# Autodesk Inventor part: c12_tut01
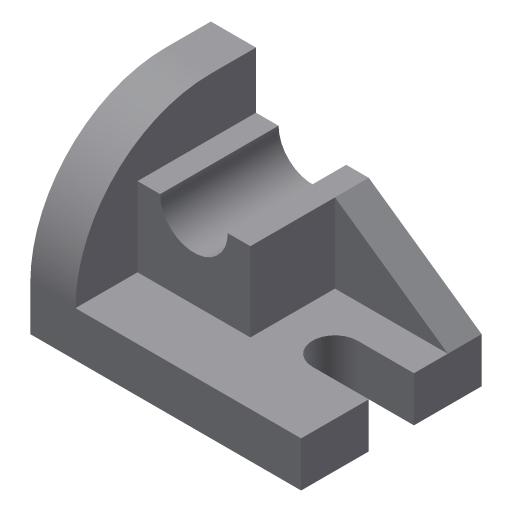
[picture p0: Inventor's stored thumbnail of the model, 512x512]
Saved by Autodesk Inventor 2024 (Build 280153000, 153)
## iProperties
Shininess: 77.0
Length Units: 11269
Angle Units: 11279
Time Units: 11290
Mass Units: 11283
Length Display Precision: 3
Angle Display Precision: 2
Created: 2001-11
Part Number: c12_tut01
Document SubType Name: Modeling
Designer: Renu Muthoo
Density: 1 g/cm^3
Material: Generic
Appearance: Default
Density: 0.0
Volumn: 0.0
Area: 0.0
PropertySet Name: Model Information
Control State: 0
Master: False
Checked Out: False
Author: Renu Muthoo
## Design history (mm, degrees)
sketch "Sketch1"
  geometry: L1 (-48, 36)-(48, 36); L2 (48, -28)-(-48, -28); L3 (-48, -28)-(-48, 36); L4 (48, 12)-(28, 12); L5 (28, -4)-(48, -4); L6 (48, 36)-(48, 12); L7 (48, -4)-(48, -28); A1 r 8 centre (28, 4) between (28, 12) and (28, -4)
  constraints: 14 end point, 4 parallel, 3 perpendicular, 2 point on circle, 2 tangent, 1 centre point, 1 collinear, 1 horizontal
  dimensions: "d0" = 96 distance of L2.start L2.end; "d1" = 64 distance of L2.end L1.start; "d2" = 20 distance of L4.start L4.end; "d3" = 24 distance between parallel lines of L2 L5; "d4" = 16 distance between parallel lines of L4 L5
extrude "Extrusion1" new body sketch "Sketch1" distance "d5" = 16; taper "d6" = 0 deg
sketch "Sketch2"
  geometry: L1 (16, 64)-(64, 64); L2 (64, 64)-(64, 48); L3 (16, 0)-(16, 0); L4 (16, 0)-(16, 64); L5 (0, 64)-(16, 64) reference; L6 (16, 0)-(16, 64) reference; L7 (0, 0)-(16, 0) reference; L8 (0, 0)-(0, 64) reference; A1 r 48 centre (16, 48) between (16, 0) and (64, 48)
  constraints: 8 end point, 3 collinear, 3 perpendicular, 2 point on circle, 2 tangent, 1 centre point, 1 horizontal
  dimensions: "d7" = 64 distance between parallel lines of L2 L8; "d8" = 48 radius of A1
extrude "Extrusion2" join sketch "Sketch2" distance "d9" = 16; taper "d10" = 0 deg
sketch "Sketch3"
  geometry: L1 (16, -44)-(16, -16); L2 (16, -16)-(56, -16); L3 (56, -16)-(56, -44); L4 (56, -44)-(48, -44); L5 (24, -44)-(16, -44); L6 (16, -64)-(16, -16) reference; L7 (16, -16)-(96, -16) reference; A1 r 12 centre (36, -44) between (48, -44) and (24, -44)
  constraints: 10 end point, 3 collinear, 3 parallel, 2 equal length, 2 point on circle, 1 centre point, 1 perpendicular, 1 point on line, 1 vertical
  dimensions: "d11" = 28 distance of L2.end L3.end; "d12" = 8 distance of L3.end L4.end; "d13" = 24 distance of L5.start L4.end
extrude "Extrusion3" join sketch "Sketch3" distance "d14" = 42; taper "d15" = 0 deg
sketch "Sketch4"
  geometry: L1 (56, -16)-(96, -16) reference; L2 (56, -16)-(56, -44) reference; L3 (96, -16)-(56, -44)
  constraints: 2 end point
extrude "Extrusion4" join sketch "Sketch4" distance "d16" = 12; taper "d17" = 0 deg
body "Solid1"
